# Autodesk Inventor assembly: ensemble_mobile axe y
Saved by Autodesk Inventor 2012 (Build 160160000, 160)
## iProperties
Created: 2013-08
Part Number: ensemble_mobile axe y
Document SubType Name: Assembly
Designer: hilarion
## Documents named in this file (1)
- D:\dominique\travail\année 2013-2014\TSTI2D\ITEC\Révision inventor\webcam motorisé\Composants importés\Webcam motorisee\ensemble_mobile axe y.iam
